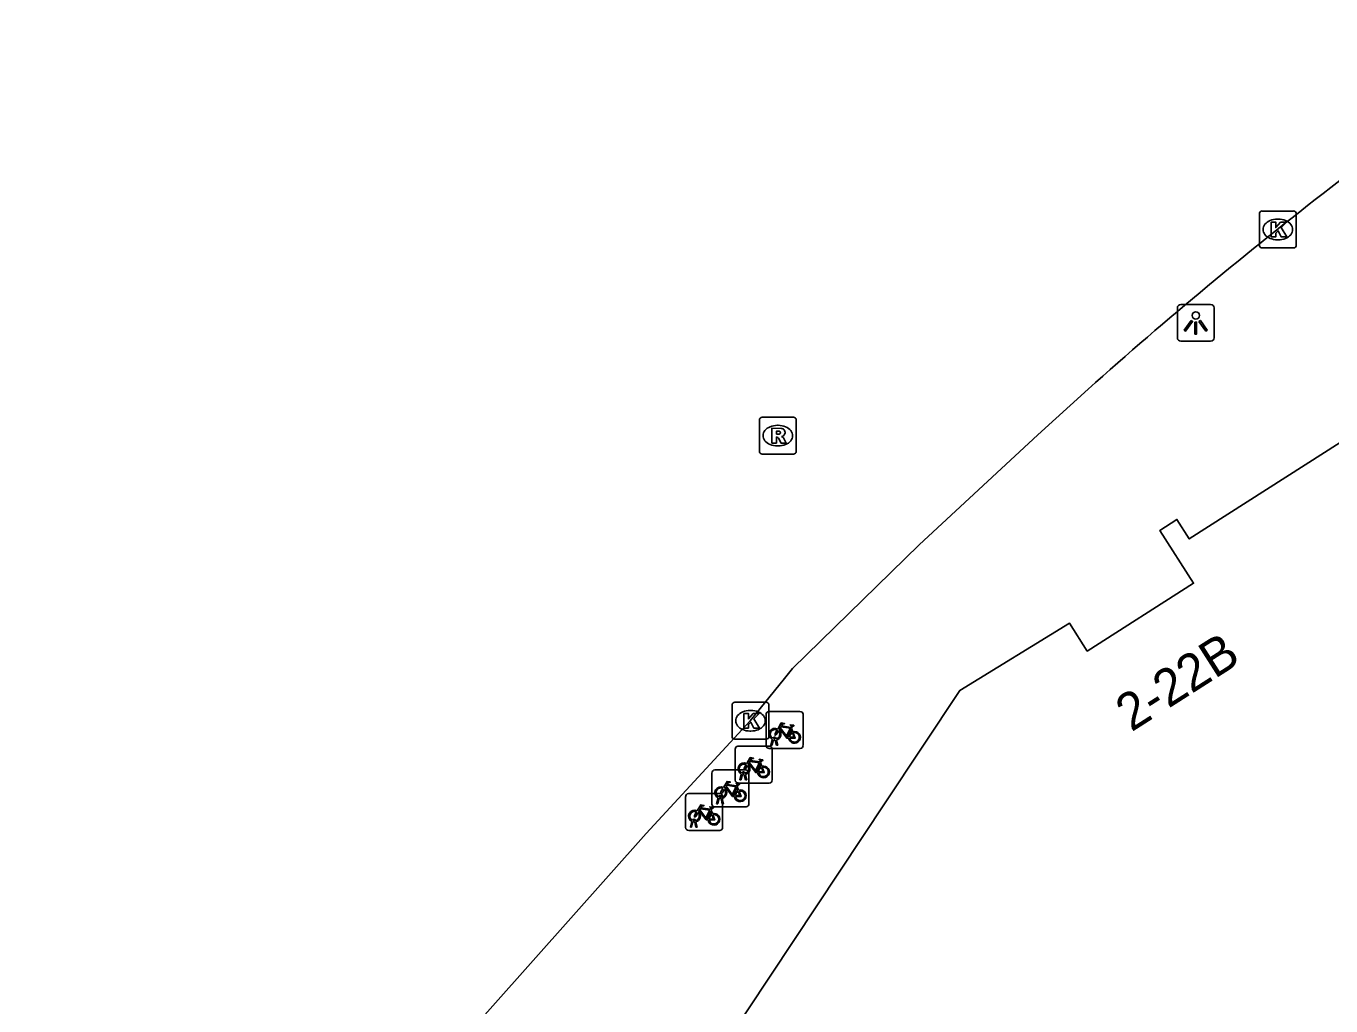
# Model space of a CAD drawing. Extents: x 159822 to 160765, y 380693 to 381634.
# Drawn here: x 160241.47 to 160276.83, y 381592.64 to 381619.18 of the extents above; entities that cross this region are included whole.
import ezdxf

# ---------------------------------------------------------------- set-up
doc = ezdxf.new("R2010")
doc.units = 0
for name, color, linetype in [('IMGEO_Fietsenrek', 7, 'Continuous'), ('IMGEO_Kolk', 7, 'Continuous'), ('IMGEO_Lichtpunt', 7, 'Continuous'), ('IMGEO_Pand', 7, 'Continuous'), ('IMGEO_Pand_nummerreeks', 7, 'Continuous'), ('IMGEO_Rijbaan_lokaal_gesloten', 7, 'Continuous'), ('IMGEO_Rioolput', 7, 'Continuous')]:
    doc.layers.add(name, color=color, linetype=linetype)

msp = doc.modelspace()

# ---------------------------------------------------------------- linework, layer by layer
at = {"layer": 'IMGEO_Fietsenrek'}
for p, q in [((160261.526, 381599.688), (160261.526, 381600.529)), ((160261.526, 381600.529), (160261.526, 381599.688)), ((160261.601, 381600.613), (160262.442, 381600.613)), ((160262.442, 381600.613), (160261.601, 381600.613)), ((160262.526, 381600.538), (160262.526, 381599.697)), ((160262.526, 381599.697), (160262.526, 381600.538)), ((160261.653, 381599.697), (160261.692, 381599.857)), ((160261.722, 381599.845), (160261.687, 381599.697)), ((160261.764, 381599.869), (160261.763, 381599.873)), ((160261.805, 381599.697), (160261.771, 381599.839)), ((160261.795, 381599.88), (160261.796, 381599.873)), ((160261.803, 381599.843), (160261.838, 381599.697)), ((160262.213, 381600.162), (160262.249, 381600.067)), ((160260.686, 381598.751), (160260.686, 381599.592)), ((160260.686, 381599.592), (160260.686, 381598.751)), ((160260.761, 381599.676), (160261.602, 381599.676)), ((160261.602, 381599.676), (160260.761, 381599.676)), ((160262.451, 381599.613), (160261.61, 381599.613)), ((160261.61, 381599.613), (160262.451, 381599.613)), ((160261.687, 381599.697), (160261.653, 381599.697)), ((160261.686, 381599.601), (160261.686, 381598.76)), ((160261.686, 381598.76), (160261.686, 381599.601)), ((160261.838, 381599.697), (160261.805, 381599.697)), ((160261.373, 381599.225), (160261.409, 381599.13)), ((160260.057, 381598.104), (160260.057, 381598.945)), ((160260.057, 381598.945), (160260.057, 381598.104)), ((160260.132, 381599.029), (160260.973, 381599.029)), ((160260.973, 381599.029), (160260.132, 381599.029)), ((160260.813, 381598.76), (160260.852, 381598.92)), ((160260.847, 381598.76), (160260.813, 381598.76)), ((160260.882, 381598.908), (160260.847, 381598.76)), ((160260.924, 381598.932), (160260.923, 381598.936)), ((160260.965, 381598.76), (160260.931, 381598.902)), ((160260.955, 381598.943), (160260.956, 381598.936)), ((160260.963, 381598.906), (160260.998, 381598.76)), ((160260.998, 381598.76), (160260.965, 381598.76)), ((160261.057, 381598.954), (160261.057, 381598.113)), ((160261.057, 381598.113), (160261.057, 381598.954)), ((160260.744, 381598.578), (160260.78, 381598.483)), ((160261.611, 381598.676), (160260.77, 381598.676)), ((160260.77, 381598.676), (160261.611, 381598.676)), ((160259.344, 381597.468), (160259.344, 381598.309)), ((160259.344, 381598.309), (160259.344, 381597.468)), ((160259.419, 381598.393), (160260.26, 381598.393)), ((160260.26, 381598.393), (160259.419, 381598.393)), ((160260.184, 381598.113), (160260.223, 381598.273)), ((160260.218, 381598.113), (160260.184, 381598.113)), ((160260.253, 381598.261), (160260.218, 381598.113)), ((160260.295, 381598.285), (160260.294, 381598.289)), ((160260.336, 381598.113), (160260.302, 381598.255)), ((160260.326, 381598.296), (160260.327, 381598.289)), ((160260.334, 381598.259), (160260.369, 381598.113)), ((160260.369, 381598.113), (160260.336, 381598.113)), ((160260.344, 381598.318), (160260.344, 381597.477)), ((160260.344, 381597.477), (160260.344, 381598.318)), ((160260.031, 381597.942), (160260.067, 381597.847)), ((160260.982, 381598.029), (160260.141, 381598.029)), ((160260.141, 381598.029), (160260.982, 381598.029)), ((160260.269, 381597.393), (160259.428, 381597.393)), ((160259.428, 381597.393), (160260.269, 381597.393)), ((160259.471, 381597.477), (160259.51, 381597.637)), ((160259.505, 381597.477), (160259.471, 381597.477)), ((160259.54, 381597.625), (160259.505, 381597.477)), ((160259.582, 381597.649), (160259.581, 381597.653)), ((160259.623, 381597.477), (160259.589, 381597.619)), ((160259.613, 381597.66), (160259.614, 381597.653)), ((160259.621, 381597.623), (160259.656, 381597.477)), ((160259.656, 381597.477), (160259.623, 381597.477))]:
    msp.add_line(p, q, dxfattribs=at)
for points in [[(160261.839, 381600.139), (160261.934, 381600.303), (160262.02, 381600.289), (160262.022, 381600.28), (160261.966, 381600.269), (160261.939, 381600.224), (160262.195, 381600.183)], [(160262.182, 381600.158), (160261.925, 381600.199), (160261.908, 381600.17), (160262.075, 381599.95), (160262.182, 381600.158)], [(160262.195, 381600.183), (160262.22, 381600.232), (160262.214, 381600.236), (160262.191, 381600.24), (160262.179, 381600.247), (160262.178, 381600.25), (160262.18, 381600.255), (160262.275, 381600.24), (160262.277, 381600.23), (160262.267, 381600.217), (160262.255, 381600.211), (160262.241, 381600.217), (160262.213, 381600.162)], [(160261.86, 381600.087), (160261.808, 381599.997), (160261.768, 381599.972), (160261.769, 381600.019), (160261.824, 381600.113)], [(160262.135, 381599.895), (160262.085, 381599.895), (160261.894, 381600.146), (160261.875, 381600.114)], [(160262.23, 381600.06), (160262.2, 381600.137), (160262.091, 381599.919), (160262.134, 381599.919)], [(160262.164, 381599.919), (160262.284, 381599.918), (160262.24, 381600.032)], [(160262.26, 381600.039), (160262.315, 381599.894), (160262.165, 381599.894)], [(160261.02, 381599.15), (160260.968, 381599.06), (160260.928, 381599.035), (160260.929, 381599.082), (160260.984, 381599.176)], [(160260.999, 381599.202), (160261.094, 381599.366), (160261.18, 381599.352), (160261.182, 381599.343), (160261.126, 381599.332), (160261.099, 381599.287), (160261.355, 381599.246)], [(160261.295, 381598.958), (160261.245, 381598.958), (160261.054, 381599.209), (160261.035, 381599.177)], [(160261.342, 381599.221), (160261.085, 381599.262), (160261.068, 381599.233), (160261.235, 381599.013), (160261.342, 381599.221)], [(160261.39, 381599.123), (160261.36, 381599.2), (160261.251, 381598.982), (160261.294, 381598.982)], [(160261.355, 381599.246), (160261.38, 381599.295), (160261.374, 381599.299), (160261.351, 381599.303), (160261.339, 381599.31), (160261.338, 381599.313), (160261.34, 381599.318), (160261.435, 381599.303), (160261.437, 381599.293), (160261.427, 381599.28), (160261.415, 381599.274), (160261.401, 381599.28), (160261.373, 381599.225)], [(160261.324, 381598.982), (160261.444, 381598.981), (160261.4, 381599.095)], [(160261.42, 381599.102), (160261.475, 381598.957), (160261.325, 381598.957)], [(160260.391, 381598.503), (160260.339, 381598.413), (160260.299, 381598.388), (160260.3, 381598.435), (160260.355, 381598.529)], [(160260.37, 381598.555), (160260.465, 381598.719), (160260.551, 381598.705), (160260.553, 381598.696), (160260.497, 381598.685), (160260.47, 381598.64), (160260.726, 381598.599)], [(160260.666, 381598.311), (160260.616, 381598.311), (160260.425, 381598.562), (160260.406, 381598.53)], [(160260.713, 381598.574), (160260.456, 381598.615), (160260.439, 381598.586), (160260.606, 381598.366), (160260.713, 381598.574)], [(160260.761, 381598.476), (160260.731, 381598.553), (160260.622, 381598.335), (160260.665, 381598.335)], [(160260.695, 381598.335), (160260.815, 381598.334), (160260.771, 381598.448)], [(160260.791, 381598.455), (160260.846, 381598.31), (160260.696, 381598.31)], [(160260.726, 381598.599), (160260.751, 381598.648), (160260.745, 381598.652), (160260.722, 381598.656), (160260.71, 381598.663), (160260.709, 381598.666), (160260.711, 381598.671), (160260.806, 381598.656), (160260.808, 381598.646), (160260.798, 381598.633), (160260.786, 381598.627), (160260.772, 381598.633), (160260.744, 381598.578)], [(160259.657, 381597.919), (160259.752, 381598.083), (160259.838, 381598.069), (160259.84, 381598.06), (160259.784, 381598.049), (160259.757, 381598.004), (160260.013, 381597.963)], [(160259.678, 381597.867), (160259.626, 381597.777), (160259.586, 381597.752), (160259.587, 381597.799), (160259.642, 381597.893)], [(160259.953, 381597.675), (160259.903, 381597.675), (160259.712, 381597.926), (160259.693, 381597.894)], [(160260, 381597.938), (160259.743, 381597.979), (160259.726, 381597.95), (160259.893, 381597.73), (160260, 381597.938)], [(160260.048, 381597.84), (160260.018, 381597.917), (160259.909, 381597.699), (160259.952, 381597.699)], [(160259.982, 381597.699), (160260.102, 381597.698), (160260.058, 381597.812)], [(160260.078, 381597.819), (160260.133, 381597.674), (160259.983, 381597.674)], [(160260.013, 381597.963), (160260.038, 381598.012), (160260.032, 381598.016), (160260.009, 381598.02), (160259.997, 381598.027), (160259.996, 381598.03), (160259.998, 381598.035), (160260.093, 381598.02), (160260.095, 381598.01), (160260.085, 381597.997), (160260.073, 381597.991), (160260.059, 381597.997), (160260.031, 381597.942)]]:
    msp.add_lwpolyline(points, dxfattribs=at)
for centre, radius, start, end in [((160261.604, 381600.535), 0.0779, 92.4484, 184.2845), ((160261.604, 381600.535), 0.0779, 92.4484, 184.2845), ((160262.448, 381600.535), 0.0779, 2.4484, 94.2845), ((160262.448, 381600.535), 0.0779, 2.4484, 94.2845), ((160261.766, 381599.998), 0.159, 62.6766, 242.1369), ((160261.766, 381599.998), 0.129, 63.3192, 238.903), ((160261.746, 381599.869), 0.0499, 12.8025, 158.6934), ((160261.766, 381599.998), 0.159, 253.9967, 271.7867), ((160261.746, 381599.869), 0.0174, 12.8025, 163.4502), ((160261.766, 381599.998), 0.129, 253.415, 269.0204), ((160261.766, 381599.998), 0.129, 283.6043, 43.4302), ((160261.766, 381599.998), 0.159, 283.5766, 46.6042), ((160262.293, 381599.914), 0.159, 113.3408, 178.3217), ((160262.293, 381599.914), 0.159, 187.0065, 105.7708), ((160262.293, 381599.914), 0.129, 113.923, 177.9556), ((160262.293, 381599.914), 0.129, 188.6715, 104.5883), ((160260.764, 381599.598), 0.0779, 92.4484, 184.2845), ((160260.764, 381599.598), 0.0779, 92.4484, 184.2845), ((160261.604, 381599.691), 0.0779, 182.4484, 274.2845), ((160261.604, 381599.691), 0.0779, 182.4484, 274.2845), ((160261.608, 381599.598), 0.0779, 2.4484, 94.2845), ((160261.608, 381599.598), 0.0779, 2.4484, 94.2845), ((160262.448, 381599.691), 0.0779, 272.4484, 4.2845), ((160262.448, 381599.691), 0.0779, 272.4484, 4.2845), ((160260.926, 381599.061), 0.159, 62.6766, 242.1369), ((160260.926, 381599.061), 0.129, 63.3192, 238.903), ((160260.926, 381599.061), 0.129, 283.6043, 43.4302), ((160260.926, 381599.061), 0.159, 283.5766, 46.6042), ((160261.453, 381598.977), 0.159, 113.3408, 178.3217), ((160261.453, 381598.977), 0.159, 187.0065, 105.7708), ((160260.135, 381598.951), 0.0779, 92.4484, 184.2845), ((160260.135, 381598.951), 0.0779, 92.4484, 184.2845), ((160260.906, 381598.932), 0.0499, 12.8025, 158.6934), ((160260.926, 381599.061), 0.159, 253.9967, 271.7867), ((160260.906, 381598.932), 0.0174, 12.8025, 163.4502), ((160260.926, 381599.061), 0.129, 253.415, 269.0204), ((160260.979, 381598.951), 0.0779, 2.4484, 94.2845), ((160260.979, 381598.951), 0.0779, 2.4484, 94.2845), ((160261.453, 381598.977), 0.129, 113.923, 177.9556), ((160261.453, 381598.977), 0.129, 188.6715, 104.5883), ((160261.608, 381598.754), 0.0779, 272.4484, 4.2845), ((160261.608, 381598.754), 0.0779, 272.4484, 4.2845), ((160260.297, 381598.414), 0.159, 62.6766, 242.1369), ((160260.297, 381598.414), 0.129, 63.3192, 238.903), ((160260.297, 381598.414), 0.129, 283.6043, 43.4302), ((160260.297, 381598.414), 0.159, 283.5766, 46.6042), ((160260.824, 381598.33), 0.159, 113.3408, 178.3217), ((160260.824, 381598.33), 0.159, 187.0065, 105.7708), ((160260.764, 381598.754), 0.0779, 182.4484, 274.2845), ((160260.764, 381598.754), 0.0779, 182.4484, 274.2845), ((160260.824, 381598.33), 0.129, 113.923, 177.9556), ((160260.824, 381598.33), 0.129, 188.6715, 104.5883), ((160259.422, 381598.315), 0.0779, 92.4484, 184.2845), ((160259.422, 381598.315), 0.0779, 92.4484, 184.2845), ((160260.135, 381598.107), 0.0779, 182.4484, 274.2845), ((160260.135, 381598.107), 0.0779, 182.4484, 274.2845), ((160260.277, 381598.285), 0.0499, 12.8025, 158.6934), ((160260.297, 381598.414), 0.159, 253.9967, 271.7867), ((160260.266, 381598.315), 0.0779, 2.4484, 94.2845), ((160260.266, 381598.315), 0.0779, 2.4484, 94.2845), ((160260.277, 381598.285), 0.0174, 12.8025, 163.4502), ((160260.297, 381598.414), 0.129, 253.415, 269.0204), ((160260.979, 381598.107), 0.0779, 272.4484, 4.2845), ((160260.979, 381598.107), 0.0779, 272.4484, 4.2845), ((160259.584, 381597.778), 0.159, 62.6766, 242.1369), ((160259.584, 381597.778), 0.129, 63.3192, 238.903), ((160259.564, 381597.649), 0.0499, 12.8025, 158.6934), ((160259.584, 381597.778), 0.129, 283.6043, 43.4302), ((160259.584, 381597.778), 0.159, 283.5766, 46.6042), ((160260.111, 381597.694), 0.159, 113.3408, 178.3217), ((160260.111, 381597.694), 0.159, 187.0065, 105.7708), ((160260.111, 381597.694), 0.129, 113.923, 177.9556), ((160260.111, 381597.694), 0.129, 188.6715, 104.5883), ((160259.422, 381597.471), 0.0779, 182.4484, 274.2845), ((160259.422, 381597.471), 0.0779, 182.4484, 274.2845), ((160259.584, 381597.778), 0.159, 253.9967, 271.7867), ((160259.564, 381597.649), 0.0174, 12.8025, 163.4502), ((160259.584, 381597.778), 0.129, 253.415, 269.0204), ((160260.266, 381597.471), 0.0779, 272.4484, 4.2845), ((160260.266, 381597.471), 0.0779, 272.4484, 4.2845)]:
    msp.add_arc(centre, radius, start, end, dxfattribs=at)
at = {"layer": 'IMGEO_Kolk'}
for p, q in [((160274.891, 381613.249), (160274.891, 381614.101)), ((160274.966, 381614.175), (160275.818, 381614.175)), ((160275.892, 381614.101), (160275.892, 381613.249)), ((160275.379, 381613.955), (160275.404, 381613.955)), ((160275.402, 381613.395), (160275.377, 381613.395)), ((160275.818, 381613.175), (160274.966, 381613.175)), ((160260.6, 381599.937), (160260.6, 381600.789)), ((160260.675, 381600.863), (160261.527, 381600.863)), ((160261.088, 381600.643), (160261.113, 381600.643)), ((160261.601, 381600.789), (160261.601, 381599.937)), ((160261.527, 381599.863), (160260.675, 381599.863)), ((160261.111, 381600.083), (160261.086, 381600.083))]:
    msp.add_line(p, q, dxfattribs=at)
for points in [[(160274.891, 381613.249), (160274.891, 381614.101)], [(160274.966, 381614.175), (160275.818, 381614.175)], [(160275.892, 381614.101), (160275.892, 381613.249)], [(160275.212, 381613.875), (160275.335, 381613.875), (160275.335, 381613.724), (160275.465, 381613.875), (160275.629, 381613.875), (160275.483, 381613.724), (160275.636, 381613.475), (160275.484, 381613.475), (160275.399, 381613.639), (160275.335, 381613.572), (160275.335, 381613.475), (160275.212, 381613.475), (160275.212, 381613.875)], [(160275.818, 381613.175), (160274.966, 381613.175)], [(160260.6, 381599.937), (160260.6, 381600.789)], [(160260.675, 381600.863), (160261.527, 381600.863)], [(160260.921, 381600.563), (160261.044, 381600.563), (160261.044, 381600.412), (160261.174, 381600.563), (160261.338, 381600.563), (160261.192, 381600.412), (160261.345, 381600.163), (160261.193, 381600.163), (160261.108, 381600.327), (160261.044, 381600.26), (160261.044, 381600.163), (160260.921, 381600.163), (160260.921, 381600.563)], [(160261.601, 381600.789), (160261.601, 381599.937)], [(160261.527, 381599.863), (160260.675, 381599.863)]]:
    msp.add_lwpolyline(points, dxfattribs=at)
for centre, start, end in [((160274.968, 381614.099), 91.552, 178.448), ((160274.968, 381614.099), 91.552, 178.448), ((160275.816, 381614.099), 1.552, 88.448), ((160275.816, 381614.099), 1.552, 88.448), ((160274.968, 381613.251), 181.552, 268.448), ((160274.968, 381613.251), 181.552, 268.448), ((160275.816, 381613.251), 271.552, 358.448), ((160275.816, 381613.251), 271.552, 358.448), ((160260.677, 381600.787), 91.552, 178.448), ((160260.677, 381600.787), 91.552, 178.448), ((160261.525, 381600.787), 1.552, 88.448), ((160261.525, 381600.787), 1.552, 88.448), ((160260.677, 381599.939), 181.552, 268.448), ((160260.677, 381599.939), 181.552, 268.448), ((160261.525, 381599.939), 271.552, 358.448), ((160261.525, 381599.939), 271.552, 358.448)]:
    msp.add_arc(centre, 0.0765, start, end, dxfattribs=at)
for centre, major_axis, ratio, start_param, end_param in [((160275.378, 381613.675), (-0.387, 0.002), 0.722429, 4.712389, 7.853982), ((160275.403, 381613.675), (-0.39, 0.002), 0.717154, 1.570796, 4.712389), ((160261.087, 381600.363), (-0.387, 0.002), 0.722429, 4.712389, 7.853982), ((160261.112, 381600.363), (-0.39, 0.002), 0.717154, 1.570796, 4.712389)]:
    msp.add_ellipse(centre, major_axis=major_axis, ratio=ratio, start_param=start_param, end_param=end_param, dxfattribs=at)
at = {"layer": 'IMGEO_Lichtpunt'}
for p, q in [((160272.669, 381611.548), (160272.669, 381610.741)), ((160272.669, 381611.548), (160272.669, 381610.741)), ((160273.571, 381611.643), (160272.763, 381611.643)), ((160273.571, 381611.643), (160272.763, 381611.643)), ((160273.665, 381610.741), (160273.665, 381611.548)), ((160273.665, 381610.741), (160273.665, 381611.548)), ((160272.763, 381610.647), (160273.571, 381610.647)), ((160272.763, 381610.647), (160273.571, 381610.647))]:
    msp.add_line(p, q, dxfattribs=at)
for points in [[(160273.043, 381611.212), (160273.082, 381611.184), (160272.894, 381610.922), (160272.856, 381610.949), (160273.043, 381611.212)], [(160273.145, 381611.164), (160273.192, 381611.164), (160273.192, 381610.842), (160273.145, 381610.842), (160273.145, 381611.164)], [(160273.255, 381611.184), (160273.293, 381611.211), (160273.48, 381610.949), (160273.441, 381610.921), (160273.255, 381611.184)]]:
    msp.add_lwpolyline(points, dxfattribs=at)
msp.add_circle((160273.168, 381611.346), 0.0994, dxfattribs=at)
for centre, start, end in [((160272.763, 381611.548), 90, 180), ((160272.763, 381611.548), 90, 180), ((160273.571, 381611.548), 0, 90), ((160273.571, 381611.548), 0, 90), ((160272.763, 381610.741), 180, 270), ((160272.763, 381610.741), 180, 270), ((160273.571, 381610.741), 270, 0), ((160273.571, 381610.741), 270, 360)]:
    msp.add_arc(centre, 0.0946, start, end, dxfattribs=at)
at = {"layer": 'IMGEO_Pand'}
msp.add_lwpolyline([(160241.47, 381562.064), (160246.992, 381570.385), (160247.789, 381569.856), (160249.935, 381573.09), (160249.093, 381573.648), (160251.782, 381577.699), (160251.301, 381578.018), (160259.068, 381589.723), (160259.61, 381589.363), (160260.259, 381590.341), (160259.786, 381590.654), (160264.753, 381598.139), (160266.775, 381601.186), (160269.744, 381603.009), (160270.227, 381602.25), (160273.11, 381604.089), (160272.195, 381605.522), (160272.656, 381605.816), (160272.991, 381605.29), (160287.982, 381614.855), (160287.579, 381615.486), (160288.127, 381615.836)], dxfattribs=at)
at = {"layer": 'IMGEO_Rijbaan_lokaal_gesloten'}
for points in [[(160276.83, 381614.811), (160282.438, 381619.185)], [(160249.207, 381588.52), (160249.27, 381588.472), (160250.257, 381588.614), (160250.938, 381588.955), (160252.08, 381590.347), (160258.275, 381597.311), (160261.096, 381600.364), (160262.02, 381601.508), (160262.237, 381601.776), (160265.668, 381605.128), (160268.887, 381608.106), (160270.251, 381609.347)]]:
    msp.add_lwpolyline(points, dxfattribs=at)
msp.add_arc((160347.275, 381523.299), 115.486, 127.5884, 131.83231, dxfattribs=at)
at = {"layer": 'IMGEO_Rioolput'}
for p, q in [((160261.341, 381607.662), (160261.341, 381608.514)), ((160261.416, 381608.588), (160262.268, 381608.588)), ((160261.829, 381608.368), (160261.854, 381608.368)), ((160262.342, 381608.514), (160262.342, 381607.662)), ((160261.852, 381607.808), (160261.827, 381607.808)), ((160262.268, 381607.588), (160261.416, 381607.588))]:
    msp.add_line(p, q, dxfattribs=at)
for points in [[(160261.341, 381607.662), (160261.341, 381608.514)], [(160261.416, 381608.588), (160262.268, 381608.588)], [(160262.342, 381608.514), (160262.342, 381607.662)], [(160261.93, 381608.286), (160261.678, 381608.288), (160261.678, 381607.888)], [(160261.678, 381607.888), (160261.802, 381607.888), (160261.802, 381608.05), (160261.813, 381608.05)], [(160261.856, 381608.207), (160261.802, 381608.207), (160261.802, 381608.126)], [(160261.802, 381608.126), (160261.854, 381608.126)], [(160261.86, 381608.021), (160261.931, 381607.888), (160262.071, 381607.888), (160262.006, 381608.014)], [(160262.268, 381607.588), (160261.416, 381607.588)]]:
    msp.add_lwpolyline(points, dxfattribs=at)
for centre, radius, start, end in [((160261.418, 381608.512), 0.0765, 91.552, 178.448), ((160261.418, 381608.512), 0.0765, 91.552, 178.448), ((160262.266, 381608.512), 0.0765, 1.552, 88.448), ((160262.266, 381608.512), 0.0765, 1.552, 88.448), ((160261.812, 381607.997), 0.0533, 26.0293, 88.6989), ((160261.838, 381608.315), 0.19, 274.7715, 282.9687), ((160261.862, 381608.111), 0.0964, 77.0061, 93.1865), ((160261.876, 381608.168), 0.0378, 276.6634, 79.6772), ((160261.929, 381608.176), 0.109, 350.3612, 89.416), ((160261.927, 381608.176), 0.112, 277.5842, 350.9817), ((160261.911, 381607.961), 0.108, 29.5134, 73.7905), ((160261.418, 381607.664), 0.0765, 181.552, 268.448), ((160261.418, 381607.664), 0.0765, 181.552, 268.448), ((160262.266, 381607.664), 0.0765, 271.552, 358.448), ((160262.266, 381607.664), 0.0765, 271.552, 358.448)]:
    msp.add_arc(centre, radius, start, end, dxfattribs=at)
for centre, major_axis, ratio, start_param, end_param in [((160261.828, 381608.088), (-0.387, 0.002), 0.722429, 4.712389, 7.853982), ((160261.853, 381608.088), (-0.39, 0.002), 0.717154, 1.570796, 4.712389)]:
    msp.add_ellipse(centre, major_axis=major_axis, ratio=ratio, start_param=start_param, end_param=end_param, dxfattribs=at)

# ---------------------------------------------------------------- texts
at = {"layer": 'IMGEO_Pand_nummerreeks'}
msp.add_text('2-22B', height=1, rotation=32.5329, dxfattribs=at).set_placement((160271.423, 381600.047))

doc.saveas('drawing.dxf')
